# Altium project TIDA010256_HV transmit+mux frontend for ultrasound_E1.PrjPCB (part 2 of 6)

## Sheet 12_LowVoltage_PowerSupplies01.SchDoc
size 431 x 279 mm; Date: Not shown in title block; ApprovedBy: Not shown in title block; CheckedBy: Not shown in title block; Author: Not shown in title block; CompanyName: Not shown in title block; Engineer: Not shown in title block; Organization: Not shown in title block; Address1: Not shown in title block; Address2: Not shown in title block; Address3: Not shown in title block; Address4: Not shown in title block; DocumentNumber: 4; Revision: Use project parameter SCH_Rev; SheetNumber: 4; SheetTotal: 18; PageSetup: Record=PageOptions¦CenterHorizontal=True¦CenterVertical=True¦PrintScale=1.00¦XCorrection=1.00¦YCorrection=1.00¦PrintKind=0¦BorderSize=5000000¦LeftOffset=0¦BottomOffset=0¦Orientation=2¦PaperLength=1000¦PaperWidth=1000¦Scale=100¦PaperSource=15¦PrintQuality=600¦MediaType=1¦DitherType=10¦PaperKind=Letter¦PrintScaleMode=1
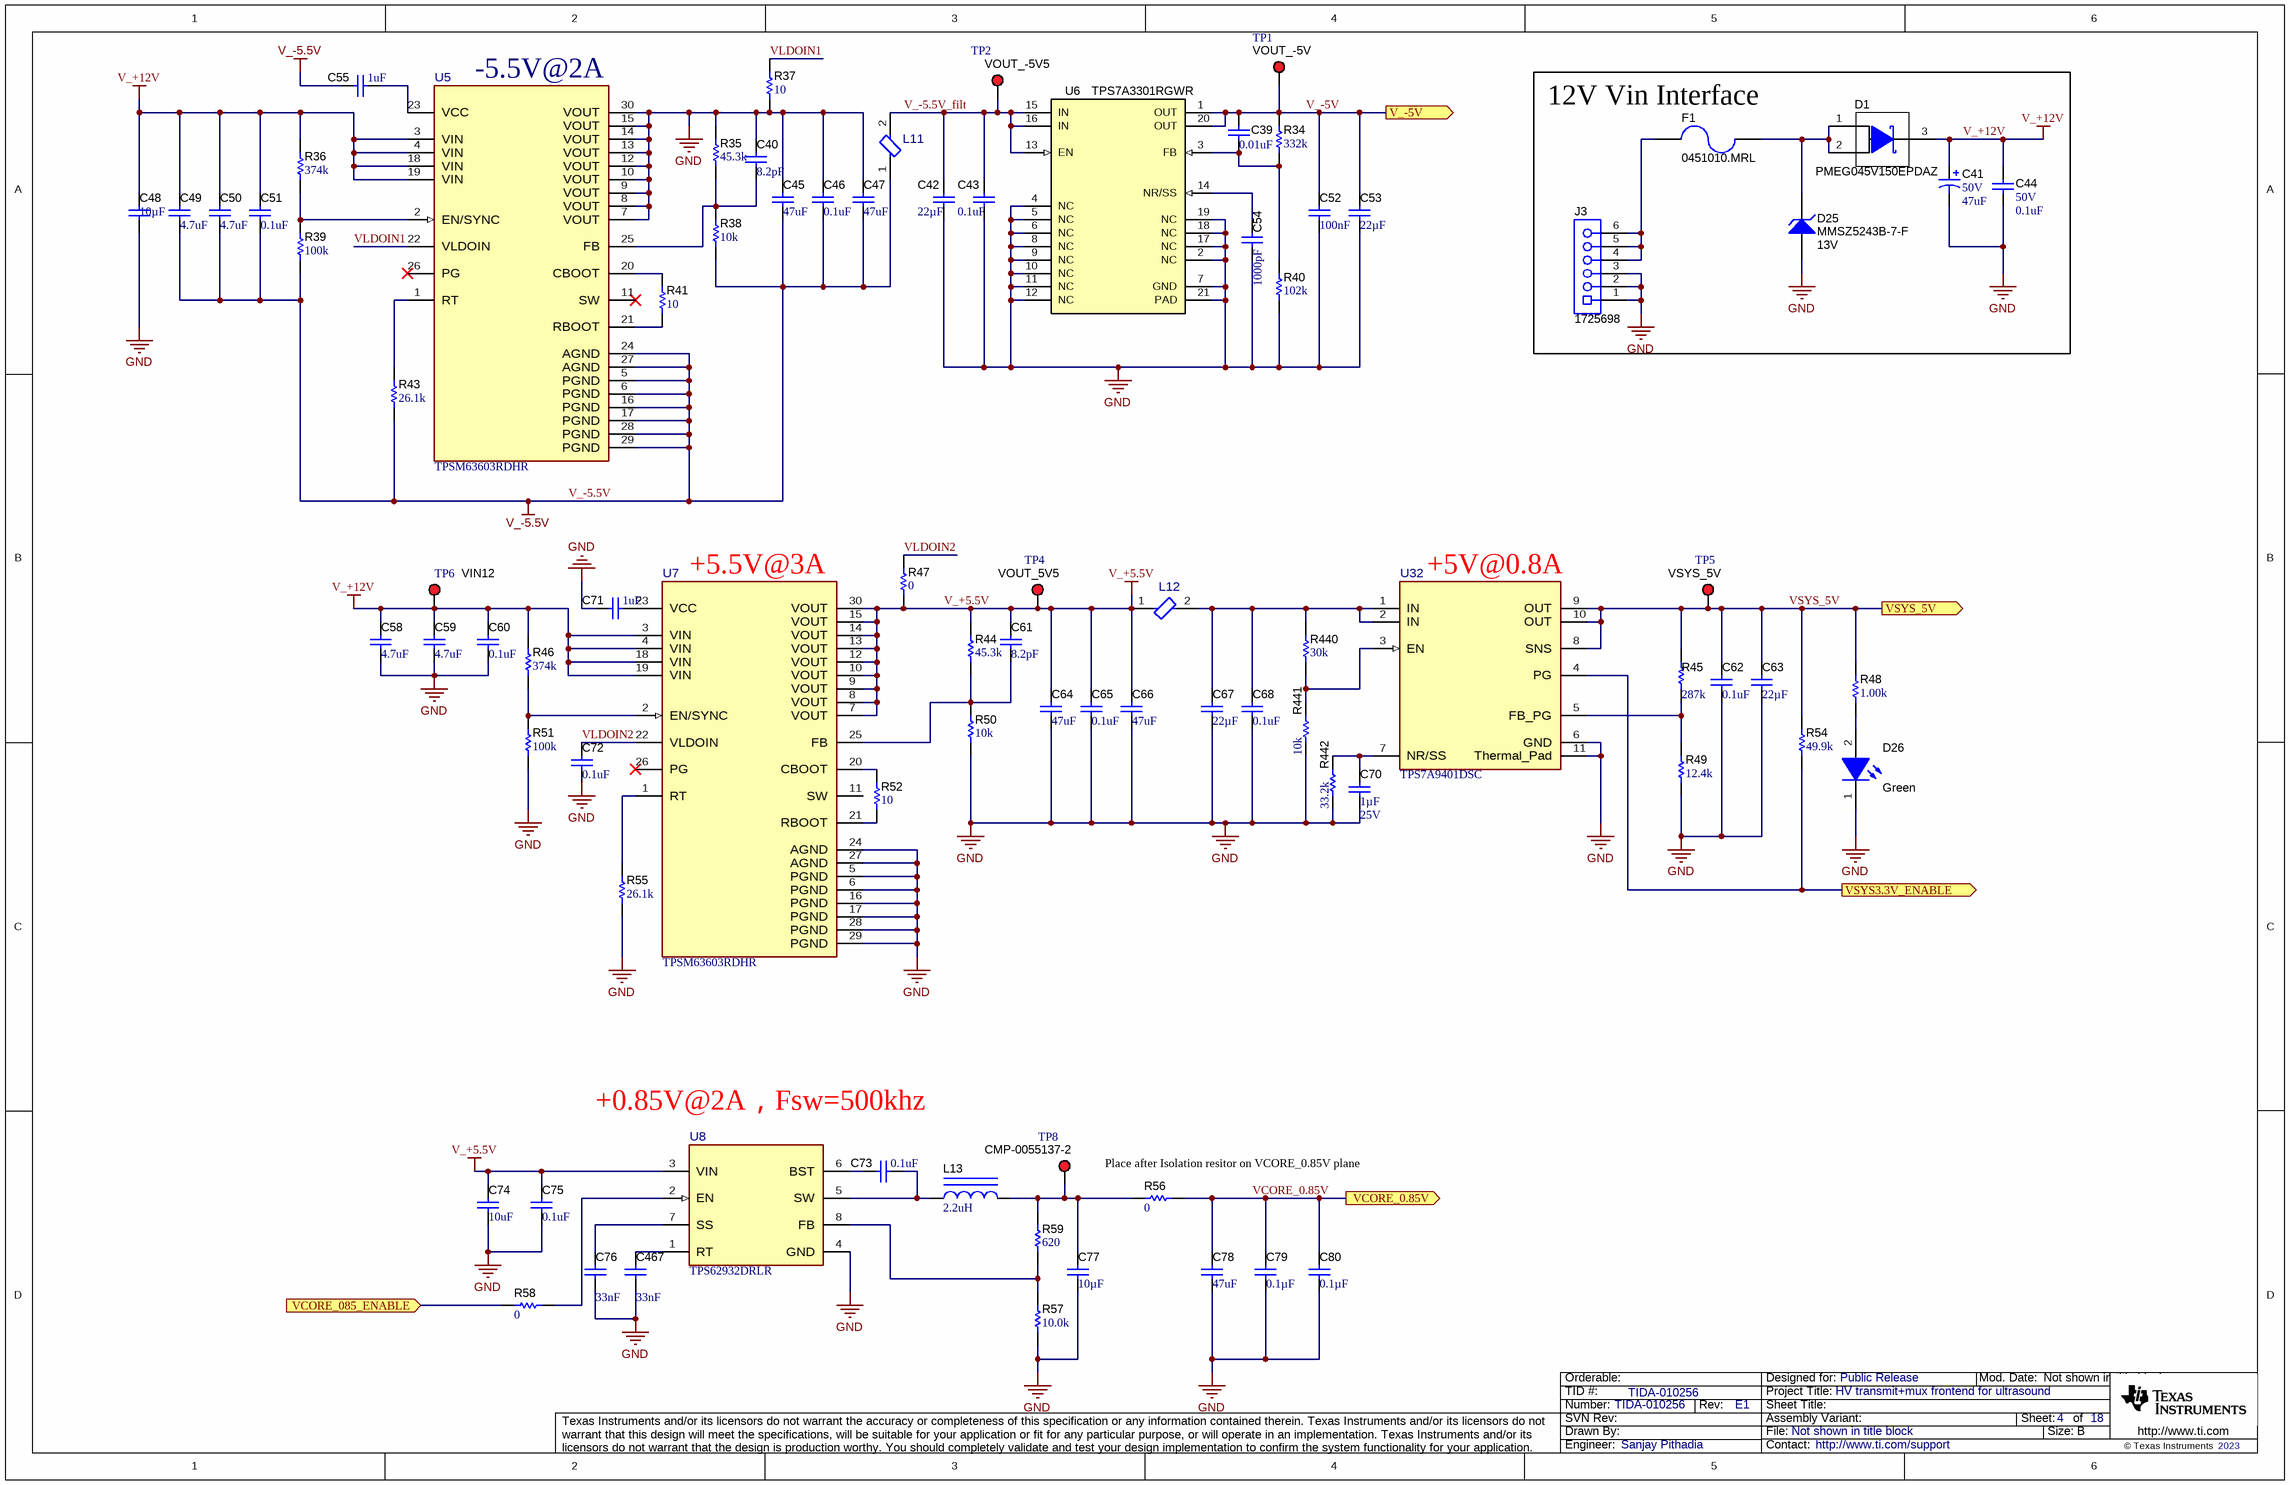
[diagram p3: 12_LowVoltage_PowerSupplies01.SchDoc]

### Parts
C39  ValueDisplayed: 0.01uF  [0603]  (hidden comment: C0603C103K4RACTU)
C40  ValueDisplayed: 8.2pF  [0402]  (hidden comment: GRM1555C1E8R2CA01D)
C41  VDC_V: 50V  ValueDisplayed: 47uF  [Panasonic_D]  (hidden comment: EEEFT1H470AP)
C42  ValueDisplayed: 22µF  [0603]  (hidden comment: CL10A226MO7JZNC)
C43  ValueDisplayed: 0.1uF  [0603]  (hidden comment: C0603C104M4RACTU)
C44  VDC_V: 50V  ValueDisplayed: 0.1uF  [0603]  (hidden comment: C1608X5R1H104K080AA)
C45  ValueDisplayed: 47uF  [1206_190]  (hidden comment: C3216X5R1E476M160AC)
C46  ValueDisplayed: 0.1uF  [0805_HV]  (hidden comment: C0805C104M5RACTU)
C47  ValueDisplayed: 47uF  [1206_190]  (hidden comment: C3216X5R1E476M160AC)
C48  ValueDisplayed: 10µF  [1206_190]  (hidden comment: UMK316BBJ106KL-T)
C49  ValueDisplayed: 4.7uF  [1206_180]  (hidden comment: C3216X7R1H475K160AC)
C50  ValueDisplayed: 4.7uF  [1206_180]  (hidden comment: C3216X7R1H475K160AC)
C51  ValueDisplayed: 0.1uF  [0805_HV]  (hidden comment: C0805C104M5RACTU)
C52  Cap_F: 100nF  [0603]  (hidden comment: C0603C104K8RACTU)
C53  ValueDisplayed: 22µF  [0603]  (hidden comment: CL10A226MO7JZNC)
C54  ValueDisplayed: 1000pF  [0603]  (hidden comment: GRM1885C1E102JA01D)
C55  ValueDisplayed: 1uF  [0402]  (hidden comment: GRM155R61E105KA12D)
C58  ValueDisplayed: 4.7uF  [1206_180]  (hidden comment: C3216X7R1H475K160AC)
C59  ValueDisplayed: 4.7uF  [1206_180]  (hidden comment: C3216X7R1H475K160AC)
C60  ValueDisplayed: 0.1uF  [0805_HV]  (hidden comment: C0805C104M5RACTU)
C61  ValueDisplayed: 8.2pF  [0402]  (hidden comment: GRM1555C1E8R2CA01D)
C62  ValueDisplayed: 0.1uF  [0603]  (hidden comment: C0603C104K8RACTU)
C63  ValueDisplayed: 22µF  [0603]  (hidden comment: CL10A226MO7JZNC)
C64  ValueDisplayed: 47uF  [1206_190]  (hidden comment: C3216X5R1E476M160AC)
C65  ValueDisplayed: 0.1uF  [0805_HV]  (hidden comment: C0805C104M5RACTU)
C66  ValueDisplayed: 47uF  [1206_190]  (hidden comment: C3216X5R1E476M160AC)
C67  ValueDisplayed: 22µF  [0603]  (hidden comment: CL10A226MO7JZNC)
C68  ValueDisplayed: 0.1uF  [0603]  (hidden comment: C0603C104M4RACTU)
C70  Cap_F: 1µF  VDC_V: 25V  [0603]  (hidden comment: 06033C105KAT2A)
C71  ValueDisplayed: 1uF  [0402]  (hidden comment: GRM155R61E105KA12D)
C72  ValueDisplayed: 0.1uF  [0402]  (hidden comment: GRM155R61E105KA12D)
C73  ValueDisplayed: 0.1uF  [0402]  (hidden comment: GRM155R71A104KA01D)
C74  ValueDisplayed: 10uF  [0805_HV]  (hidden comment: C0805C106K8PACTU)
C75  ValueDisplayed: 0.1uF  [0402]  (hidden comment: GRM155R71A104KA01D)
C76  Cap_F: 33nF  [0603]  (hidden comment: CL10B333KO8NNNC)
C77  ValueDisplayed: 10µF  [0603]  (hidden comment: GRM188R61A106KE69D)
C78  ValueDisplayed: 47uF  [0603]  (hidden comment: GRM188R60J476ME15D)
C79  ValueDisplayed: 0.1µF  [0201_033]  (hidden comment: GRM033R61C104KE14D)
C80  ValueDisplayed: 0.1µF  [0201_033]  (hidden comment: GRM033R61C104KE14D)
C467  Cap_F: 33nF  [0603]  (hidden comment: CL10B333KO8NNNC)
D1  PMEG045V150EPDAZ  [SOT1289]
D25  MMSZ5243B-7-F  value 13V  [SOD-123]
D26  value Green  [WL-SMCW_GREEN]  (hidden comment: 150060VS75000)
F1  0451010.MRL  [Fuse_451_453]
J3  1725698  [Phoenix_1725698]
L11  BLM18SG700TN1D  [FP-BLM18SG700TN1D_0603-MFG]  (value not drawn)
L12  BLM18SG700TN1D  [FP-BLM18SG700TN1D_0603-MFG]  (value not drawn)
L13  ValueDisplayed: 2.2uH  [SRU1038]  (hidden comment: SRU1038-2R2Y)
R34  ValueDisplayed: 332k  [0603]  (hidden comment: CRCW060349K9FKEA)
R35  ValueDisplayed: 45.3k  [0603]  (hidden comment: CRCW060345K3FKEA)
R36  ValueDisplayed: 374k  [0603]  (hidden comment: RT0603BRD07142KL)
R37  ValueDisplayed: 10  [0402]  (hidden comment: CRCW040210R0JNED)
R38  ValueDisplayed: 10k  [0603]  (hidden comment: CRCW060349K9FKEA)
R39  ValueDisplayed: 100k  [0603]  (hidden comment: TNPW0603100KBEEA)
R40  ValueDisplayed: 102k  [0603]  (hidden comment: CRCW060349K9FKEA)
R41  ValueDisplayed: 10  [0402]  (hidden comment: CRCW040210R0JNED)
R43  ValueDisplayed: 26.1k  [0603]  (hidden comment: RT0603BRD0726K1L)
R44  ValueDisplayed: 45.3k  [0603]  (hidden comment: CRCW060349K9FKEA)
R45  ValueDisplayed: 287k  [0603]  (hidden comment: RC0603FR-07287KL)
R46  ValueDisplayed: 374k  [0603]  (hidden comment: RT0603BRD07142KL)
R47  ValueDisplayed: 0  [0603]  (hidden comment: ERJ-3GEY0R00V)
R48  ValueDisplayed: 1.00k  [0603]  (hidden comment: RC0603FR-071KL)
R49  ValueDisplayed: 12.4k  [0603]  (hidden comment: RC0603FR-0712K4L)
R50  ValueDisplayed: 10k  [0603]  (hidden comment: CRCW060349K9FKEA)
R51  ValueDisplayed: 100k  [0603]  (hidden comment: TNPW0603100KBEEA)
R52  ValueDisplayed: 10  [0402]  (hidden comment: CRCW040210R0JNED)
R54  ValueDisplayed: 49.9k  [0603]  (hidden comment: ERJ-3EKF4992V)
R55  ValueDisplayed: 26.1k  [0603]  (hidden comment: RT0603BRD0726K1L)
R56  ValueDisplayed: 0  [1210]  (hidden comment: MCR25JZHJ000)
R57  ValueDisplayed: 10.0k  [0402]  (hidden comment: CRCW040210K0FKED)
R58  ValueDisplayed: 0  [0603]  (hidden comment: CRCW060349K9FKEA)
R59  ValueDisplayed: 620  [0603]  (hidden comment: RC0603FR-07620RL)
R440  ValueDisplayed: 30k  [0603]  (hidden comment: CRCW060330K0JNEA)
R441  ValueDisplayed: 10k  [0603]  (hidden comment: CRCW060310K0JNEA)
R442  ValueDisplayed: 33.2k  [0603]  (hidden comment: RC0603FR-0733K2L)
TP1  VOUT_-5V  [Keystone5000]
TP2  VOUT_-5V5  [Keystone5000]
TP4  VOUT_5V5  [Keystone5000]
TP5  VSYS_5V  [Keystone5000]
TP6  VIN12  [Keystone5000]
TP8  CMP-0055137-2  [Keystone5000]
U5  TPSM63603RDHR  [RDH0030A-MFG]
U6  TPS7A3301RGWR  [RGW0020A]
U7  TPSM63603RDHR  [RDH0030A-MFG]
U8  TPS62932DRLR  [DRL0008A-MFG]
U32  TPS7A9401DSC  [DSC0010J-MFG]

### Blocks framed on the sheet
12V Vin Interface: C41 C44 D1 D25 F1 J3

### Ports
V_-5V (out), VCORE_0.85V (out), VCORE_085_ENABLE (in), VSYS3.3V_ENABLE (out), VSYS_5V (out)

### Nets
GND: C40.1 C41.2(-) C42.2 C43.2 C44.2 C45.1 C46.1 C47.1 C48.2 C52.2 C53.2 C54.2 C58.2 C59.2 C60.2 C62.2 C63.2 C64.2 C65.2 C66.2 C67.2 C68.2 C70.2 C71.2 C72.2 C74.2 C75.2 C76.2 C77.2 C78.2 C79.2 C80.2 C467.2 D25.2(A) D26.1(K) J3.1 J3.2 J3.3 R35.2 R37.1 R40.1 R49.1 R50.1 R51.1 R55.1 R57.1 R441.1 R442.1 U5.7(VOUT) U5.8(VOUT) U5.9(VOUT) U5.10(VOUT) U5.12(VOUT) U5.13(VOUT) U5.14(VOUT) U5.15(VOUT) U5.30(VOUT) U6.2(NC) U6.4(NC) U6.5(NC) U6.6(NC) U6.7(GND) U6.8(NC) U6.9(NC) U6.10(NC) U6.11(NC) U6.12(NC) U6.17(NC) U6.18(NC) U6.19(NC) U6.21(PAD) U7.5(PGND) U7.6(PGND) U7.16(PGND) U7.17(PGND) U7.24(AGND) U7.27(AGND) U7.28(PGND) U7.29(PGND) U8.4(GND) U32.6(GND) U32.11(Thermal_Pad)
V_+5.5V: C61.1 C64.1 C65.1 C66.1 C74.1 C75.1 L12.1 R44.2 R47.1 TP4.1 U7.7(VOUT) U7.8(VOUT) U7.9(VOUT) U7.10(VOUT) U7.12(VOUT) U7.13(VOUT) U7.14(VOUT) U7.15(VOUT) U7.30(VOUT) U8.3(VIN)
V_+12V: C41.1(+) C44.1 C48.1 C49.1 C50.1 C51.1 C58.1 C59.1 C60.1 D1.3(K) R36.2 R46.2 TP6.1 U5.3(VIN) U5.4(VIN) U5.18(VIN) U5.19(VIN) U7.3(VIN) U7.4(VIN) U7.18(VIN) U7.19(VIN)
V_-5.5V: C45.2 C46.2 C47.2 C49.2 C50.2 C51.2 C55.2 L11.1 R38.1 R39.1 R43.1 U5.5(PGND) U5.6(PGND) U5.16(PGND) U5.17(PGND) U5.24(AGND) U5.27(AGND) U5.28(PGND) U5.29(PGND)
V_-5.5V_filt: C42.1 C43.1 L11.2 TP2.1 U6.13(EN) U6.15(IN) U6.16(IN)
V_-5V: C39.1 C52.1 C53.1 R34.2 TP1.1 U6.1(OUT) U6.20(OUT) ; port V_-5V
VCORE_0.85V: C78.1 C79.1 C80.1 R56.2 ; port VCORE_0.85V
VLDOIN1: R37.2 U5.22(VLDOIN)
VLDOIN2: C72.1 R47.2 U7.22(VLDOIN)
VSYS_5V: C62.1 C63.1 R45.2 R48.2 R54.2 TP5.1 U32.8(SNS) U32.9(OUT) U32.10(OUT) ; port VSYS_5V
NetC39_2: C39.2 R34.1 R40.2 U6.3(FB)
NetC40_2: C40.2 R35.1 R38.2 U5.25(FB)
NetC54_1: C54.1 U6.14(NR/SS)
NetC55_1: C55.1 U5.23(VCC)
NetC61_2: C61.2 R44.1 R50.2 U7.25(FB)
NetC67_1: C67.1 C68.1 L12.2 R440.2 U32.1(IN) U32.2(IN)
NetC70_1: C70.1 R442.2 U32.7(NR/SS)
NetC71_1: C71.1 U7.23(VCC)
NetC73_1: C73.1 U8.6(BST)
NetC73_2: C73.2 L13.1 U8.5(SW)
NetC76_1: C76.1 U8.7(SS)
NetC77_1: C77.1 L13.2 R56.1 R59.2 TP8.1
NetC467_1: C467.1 U8.1(RT)
NetD1_1: D1.1(A) D1.2(A) D25.1(K) F1.1
NetD26_2: D26.2(A) R48.1
NetF1_2: F1.2 J3.4 J3.5 J3.6
NetR36_1: R36.1 R39.2 U5.2(EN/SYNC)
NetR41_1: R41.1 U5.21(RBOOT)
NetR41_2: R41.2 U5.20(CBOOT)
NetR43_2: R43.2 U5.1(RT)
NetR45_1: R45.1 R49.2 U32.5(FB_PG)
NetR46_1: R46.1 R51.2 U7.2(EN/SYNC)
NetR52_1: R52.1 U7.21(RBOOT)
NetR52_2: R52.2 U7.20(CBOOT)
NetR54_1: R54.1 U32.4(PG) ; port VSYS3.3V_ENABLE
NetR55_2: R55.2 U7.1(RT)
NetR57_2: R57.2 R59.1 U8.8(FB)
NetR58_1: R58.1 U8.2(EN)
NetR58_2: R58.2 ; port VCORE_085_ENABLE
NetR440_1: R440.1 R441.2 U32.3(EN)

Not connected (* = marked no-connect by the designer): U5 11(SW)* 26(PG)*; U7 11(SW) 26(PG)*

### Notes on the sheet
- (near U5) -5.5V@2A
- (near U7) +5.5V@3A
- (near U32) +5V@0.8A
- +0.85V@2A，Fsw=500khz
- Place after Isolation resitor on VCORE_0.85V plane

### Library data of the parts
C39 = CMP-0006853-4: CAP, CERM, 0.01 uF, 16 V, +/- 10%, X7R, 0603; Manufacturer: Kemet; Polarized: N; Value: 0.01uF; U/M: EA; Cap_F: 10nF; Value1: Unknown; VDC_V: 16V; TaMin_C: -55°C; TaMax_C: 125°C; SizeArea_mm2: 1.28; SizeAreaWB_mm2: 4.68; SizeX_mm: 1.6; SizeY_mm: 0.8; SizeZ_mm: 1; AEC Category: Q200
C40 C61 = CMP-0006405-2: CAP, CERM, 8.2 pF, 25 V, +/- 5%, C0G/NP0, 0402; Manufacturer: MuRata; Polarized: N; Value: 8.2pF; U/M: EA; Value1: Unknown; VDC_V: 25V; TaMin_C: -55°C; TaMax_C: 125°C; SizeArea_mm2: 0.5; SizeAreaWB_mm2: 3; SizeX_mm: 1; SizeZ_mm: 0.6; AEC Category: Q200
C41 = CMP-0011204-2: CAP, AL, 47 uF, 50 V, +/- 20%, 0.68 ohm, AEC-Q200 Grade 2, SMD; Manufacturer: Panasonic; TaMin_C: -55°C; Polarized: Y; SizeAreaWB_mm2: 73.96; U/M: EA; Value: 47uF; TaMax_C: 105°C; SizeZ_mm: 6.1; SizeX_mm: 6.6; Cap_Case: 6.3x5.8mm; SizeArea_mm2: 43.56; CompType: Capacitor; Cap_F: 47µF; IRMS_A: 195mA; AEC Grade: 2; AEC Category: Q200; ESR_ohm: 0.68
C42 C67 = CMP-0081159-1: CAP, CERM, 22 µF, 16 V,+/- 20%, X5R, 0603; Manufacturer: Samsung; Polarized: N; Value: 22uF; U/M: EA; VDC_V: 16V; TaMin_C: -55°C; TaMax_C: 85°C; SizeArea_mm2: 1.28; SizeAreaWB_mm2: 4.68; SizeX_mm: 1.6; SizeY_mm: 0.8; SizeZ_mm: 1; AEC Category: Q200
C43 C68 = CMP-0006864-4: CAP, CERM, 0.1 uF, 16 V, +/- 20%, X7R, 0603; Manufacturer: Kemet; Polarized: N; Value: 0.1uF; U/M: EA; Cap_F: 100nF; Value1: Unknown; VDC_V: 16V; TaMin_C: -55°C; TaMax_C: 125°C; SizeArea_mm2: 1.28; SizeAreaWB_mm2: 4.68; SizeX_mm: 1.6; SizeY_mm: 0.8; SizeZ_mm: 1; AEC Category: Q200
C44 = CMP-0007010-5: CAP, CERM, 0.1 uF, 50 V, +/- 10%, X5R, 0603; Manufacturer: TDK; TaMin_C: -55°C; ESR_ohm: 0.0296; Polarized: N; SizeAreaWB_mm2: 4.68; Value1: 0.0296 ohm; U/M: EA; Value: 0.1uF; TaMax_C: 85°C; SizeZ_mm: 1; SizeX_mm: 1.6; SizeY_mm: 0.8; SizeArea_mm2: 1.28; Cap_F: 100nF; IRMS_A: 9.7199dA; AEC Category: Q200
C45 C47 C64 C66 = CMP-0008656-2: CAP, CERM, 47 uF, 25 V, +/- 20%, X5R, 1206_190; Manufacturer: TDK; Polarized: N; Value: 47uF; U/M: EA; Cap_F: 47µF; Value1: Unknown; VDC_V: 25V; TaMin_C: -55°C; TaMax_C: 85°C; Cap_Case: 1206; SizeArea_mm2: 5.12; SizeAreaWB_mm2: 10.92; SizeX_mm: 3.2; SizeY_mm: 1.6; SizeZ_mm: 1.9; AEC Category: Q200
C46 C51 C60 C65 = CMP-0007727-2: CAP, CERM, 0.1 uF, 50 V, +/- 20%, X7R, 0805; Manufacturer: Kemet; Polarized: N; Value: 0.1uF; U/M: EA; Cap_F: 100nF; ESR_ohm: 64m; Value1: 0.064 ohm; VDC_V: 50V; IRMS_A: 1.64A; TaMin_C: -55°C; TaMax_C: 125°C; Cap_Case: 0805; SizeArea_mm2: 2.5; SizeAreaWB_mm2: 6.75; SizeX_mm: 2; SizeY_mm: 1.25; SizeZ_mm: 1.45; AEC Category: Q200
C48 = CMP-0086153-1: CAP, CERM, 10 µF, 50 V,+/- 10%, X5R, 1206; Manufacturer: Taiyo Yuden; Polarized: N; Value: 10uF; U/M: EA; VDC_V: 50V; TaMin_C: -55°C; TaMax_C: 85°C; Cap_Case: 1206; SizeArea_mm2: 5.12; SizeAreaWB_mm2: 10.92; SizeX_mm: 3.2; SizeY_mm: 1.6; SizeZ_mm: 1.9; AEC Category: Q200
C49 C50 C58 C59 = CMP-0008702-2: CAP, CERM, 4.7 uF, 50 V, +/- 10%, X7R, 1206; Manufacturer: TDK; Polarized: N; Value: 4.7uF; U/M: EA; Cap_F: 4.7µF; ESR_ohm: 3.158m; Value1: 0.003158 ohm; VDC_V: 50V; IRMS_A: 4.0838A; TaMin_C: -55°C; TaMax_C: 125°C; SizeArea_mm2: 5.12; SizeAreaWB_mm2: 10.92; SizeX_mm: 3.2; SizeY_mm: 1.6; SizeZ_mm: 1.8; AEC Category: Q200
C52 = CMP-0006862-5: CAP, CERM, 0.1 uF, 10 V, +/- 10%, X7R, 0603; Manufacturer: Kemet; TaMin_C: -55°C; Polarized: N; SizeAreaWB_mm2: 4.68; Value1: Unknown; U/M: EA; Value: 0.1uF; TaMax_C: 125°C; SizeZ_mm: 1; SizeX_mm: 1.6; SizeY_mm: 0.8; Value2: 10V; SizeArea_mm2: 1.28; AEC Category: Q200
C53 C63 = CMP-0081159-1: CAP, CERM, 22 µF, 16 V,+/- 20%, X5R, 0603; Manufacturer: Samsung; Value: 22uF; VDC_V: 16V; SizeZ_mm: 1; AEC Qualified: N; SizeAreaWB_mm2: 4.68; SizeArea_mm2: 1.28; AEC Category: Q200; TaMax_C: 85°C; TaMin_C: -55°C; SizeY_mm: 0.8; U/M: EA; SizeX_mm: 1.6
C54 = CMP-0007159-4: CAP, CERM, 1000 pF, 25 V, +/- 5%, C0G/NP0, 0603; Manufacturer: MuRata; TaMin_C: -55°C; Polarized: N; SizeAreaWB_mm2: 4.68; Value1: Unknown; U/M: EA; Value: 1000pF; TaMax_C: 125°C; SizeZ_mm: 1; SizeX_mm: 1.6; SizeY_mm: 0.8; Value2: 25V; SizeArea_mm2: 1.28; Cap_F: 1nF; AEC Category: Q200
C55 C71 = CMP-0006608-2: CAP, CERM, 1 uF, 25 V, +/- 10%, X5R, 0402; Manufacturer: MuRata; Polarized: N; Value: 1uF; U/M: EA; Cap_F: 1µF; Value1: Unknown; VDC_V: 25V; TaMin_C: -55°C; TaMax_C: 85°C; SizeArea_mm2: 0.5; SizeAreaWB_mm2: 3; SizeX_mm: 1; SizeZ_mm: 0.6; AEC Category: Q200
C62 = CMP-0006862-5: CAP, CERM, 0.1 uF, 10 V, +/- 10%, X7R, 0603; Manufacturer: Kemet; Polarized: N; Value: 0.1uF; U/M: EA; Cap_F: 100nF; Value1: Unknown; VDC_V: 10V; TaMin_C: -55°C; TaMax_C: 125°C; SizeArea_mm2: 1.28; SizeAreaWB_mm2: 4.68; SizeX_mm: 1.6; SizeY_mm: 0.8; SizeZ_mm: 1; AEC Category: Q200
C70 = CMP-0006754-4: CAP, CERM, 1 uF, 25 V, +/- 10%, X7R, 0603; Manufacturer: AVX; TaMin_C: -55°C; Polarized: N; SizeAreaWB_mm2: 4.68; Value1: Unknown; U/M: EA; Value: 1uF; TaMax_C: 125°C; SizeZ_mm: 1; SizeX_mm: 1.6; SizeY_mm: 0.8; SizeArea_mm2: 1.28; AEC Category: Q200
C72 = CMP-0006608-2: CAP, CERM, 0.1 uF, 25 V, +/- 10%, X5R, 0402; Manufacturer: MuRata; Polarized: N; Value: 1uF; U/M: EA; Cap_F: 1µF; Value1: Unknown; VDC_V: 25V; TaMin_C: -55°C; TaMax_C: 85°C; SizeArea_mm2: 0.5; SizeAreaWB_mm2: 3; SizeX_mm: 1; SizeZ_mm: 0.6; AEC Category: Q200
C73 C75 = CMP-0006629-2: CAP, CERM, 0.1 uF, 10 V, +/- 10%, X7R, 0402; Manufacturer: MuRata; TaMin_C: -55°C; Polarized: N; SizeAreaWB_mm2: 3; Value1: Unknown; U/M: EA; Value: 0.1uF; TaMax_C: 125°C; SizeZ_mm: 0.6; SizeX_mm: 1; SizeY_mm: 0.5; Value2: 10V; Cap_F: 100nF; AEC Category: Q200
C74 = CMP-0007732-2: CAP, CERM, 10 uF, 10 V, +/- 10%, X5R, 0805; Manufacturer: Kemet; TaMin_C: -55°C; ESR_ohm: 3m; Polarized: N; SizeAreaWB_mm2: 6.75; Value1: 0.003 ohm; U/M: EA; Value: 10uF; TaMax_C: 85°C; SizeZ_mm: 1.45; SizeX_mm: 2; SizeY_mm: 1.25; Cap_Case: 0805; Value2: 10V; SizeArea_mm2: 2.5; Cap_F: 10µF; IRMS_A: 11.43A; AEC Category: Q200
C76 C467 = CMP-0086223-1: CAP, CERM, 0.033 µF, 16 V,+/- 10%, X7R, 0603; Manufacturer: Samsung Electro-Mechanics; SizeArea_mm2: 1.28; SizeAreaWB_mm2: 4.68; Polarized: N; SizeX_mm: 1.6; Value2: 16V; AEC Category: Q200; TaMax_C: 125°C; TaMin_C: -55°C; Value: 0.033uF; U/M: EA; SizeZ_mm: 1; SizeY_mm: 0.8
C77 = CMP-0085855-1: CAP, CERM, 10 µF, 10 V,+/- 10%, X5R, 0603; Manufacturer: MuRata; SizeX_mm: 1.6; Value2: 10V; SizeAreaWB_mm2: 4.68; Green_REACh: Incomplete; AEC Category: Q200; SizeArea_mm2: 1.28; SizeY_mm: 0.8; Green_Lifecycle: Active; TaMax_C: 85°C; Value: 10uF; U/M: EA; Polarized: N; TaMin_C: -55°C; SizeZ_mm: 1
C78 = CMP-0007313-5: CAP, CERM, 47 uF, 6.3 V, +/- 20%, X5R, 0603; Manufacturer: MuRata; TaMin_C: -55°C; Polarized: N; SizeAreaWB_mm2: 4.68; Value1: Unknown; U/M: EA; Value: 47uF; TaMax_C: 85°C; SizeZ_mm: 1; SizeX_mm: 1.6; SizeY_mm: 0.8; Value2: 6.3V; SizeArea_mm2: 1.28; Cap_F: 47µF; AEC Category: Q200
C79 C80 = CMP-0086192-1: CAP, CERM, 0.1 µF, 16 V,+/- 10%, X5R, 0201; Manufacturer: MuRata; Value2: 16V; TaMax_C: 85°C; AEC Category: Q200; U/M: EA; SizeZ_mm: 0.33; SizeArea_mm2: 0.18; Polarized: N; SizeAreaWB_mm2: 2.08; Cap_F: 100nF; Cap_Case: 0201; SizeY_mm: 0.3; SizeX_mm: 0.6; Value: 0.1uF; TaMin_C: -55°C
D1 = CMP-0077070-3: Diode, Schottky, 45 V, 15 A, AEC-Q101, CFP15; Manufacturer: Nexperia; Io_A: 15A; Vf_V: 490mV; Vr_V: 45V; SizeX_mm: 6.5; Value: 45V; SizeArea_mm2: 27.95; Green_Lifecycle: Not Set; Value2: 0.49V; AEC Category: Q101; TJmax_C: 175°C; AEC Qualified: Y; SizeY_mm: 4.3; SizeAreaWB_mm2: 53.55; SizeZ_mm: 0.82; Green_REACh: Incomplete
D25 = CMP-0005752-4: Diode, Zener, 13 V, 500 mW, SOD-123; Manufacturer: Diodes Inc.; Value1: 0.5W; SizeAreaWB_mm2: 13.095; RJA_CperW: 350; AEC Category: Q101; SizeZ_mm: 1.35; SizeX_mm: 3.85; Power_W: 500mW; SizeArea_mm2: 6.545; SizeY_mm: 1.7
D26 = CMP-0002894-2: LED, Green, SMD; Manufacturer: Wurth Elektronik; Type: AlInGaP; Value2: 2V; Io_A: 20mA; Value1: W
F1 = CMP-0082398-1: Fuse, 10 A, 125VAC/VDC, SMD; Manufacturer: Littelfuse; Fuse Technology: Board Mount; VAC_V: 125V; SizeAreaWB_mm2: 37.989; Rtyp_Ohm: 5.6m; SizeArea_mm2: 16.409; Fuse Speed: Fast; MeltingTyp: 26.46; Irating_A: 10A; TaMax_C: 125°C; SizeZ_mm: 2.94; TaMin_C: -55°C; SizeY_mm: 2.69; Interrupt_AC: 35A; SizeX_mm: 6.1; Interrupt_DC: 50A
J3 = CMP-0055512-1: Terminal Block, 6x1, 2.54mm, TH; Manufacturer: Phoenix Contact; CNHeader: FALSE; Current_A: 6A; Cert_CSA: Y; Voltage_V: 160V; Row_Count: 1; Pitch_mm: 2.54; CT: TRUE
L11 L12 = CMP-0089431-1: 70 Ohms @ 100MHz 1 Power Line Ferrite Bead 0603 (1608 Metric) 4A 20mOhm; Manufacturer: Murata; SizeZ_mm: 0.65mm; AEC Qualified: No; Tolerance_%: 25%; DCR_ohm: 20m; Impedance At Frequency: 70Ω @ 100MHz
L13 = CMP-0057236-1: Inductor, Drum Core, Ferrite, 2.2 uH, 6.5 A, 0.0077 ohm, SMD; Manufacturer: Bourns; Isat: 6.5A @ 35% inductance drop; Irms: 6.8A @ 40C rise; Green_Lifecycle: Active; SizeAreaWB_mm2: 144; DCR_ohm: 7.7m; Green_REACh: Passed; Value: 2.2uH; Imax_A: 6.5A; SizeZ_mm: 3.8; SizeX_mm: 10; SizeArea_mm2: 100; Ind_H: 2.2µH; AEC Category: Q200
R34 = CMP-0022447-4: RES, 332k, 1%, 0.1 W, AEC-Q200 Grade 0, 0603; Manufacturer: Vishay-Dale; Value: 49.9k; Value_Code: 49k9; Power_W: 100mW; Value2: 0.1W; VDC_V: 75V; TempCo: 100 ppm/C; SizeArea_mm2: 1.28; SizeX_mm: 1.6; SizeY_mm: 0.8; SizeZ_mm: 1; EIA_Code: E96; AEC Category: Q200; AEC Qualified: Y; AEC Grade: 0
R35 = CMP-0022430-4: RES, 45.3 k, 1%, 0.1 W, AEC-Q200 Grade 0, 0603; Manufacturer: Vishay-Dale; Power_W: 100mW; TempCo: 100 ppm/C; Value_Code: 45k3; Value: 45.3k; EIA_Code: E96; SizeX_mm: 1.6; SizeY_mm: 0.8; SizeZ_mm: 1; Value2: 0.1W; SizeArea_mm2: 1.28; AEC Qualified: Y; VDC_V: 75V; AEC Category: Q200; AEC Grade: 0
R36 R46 = CMP-0023744-2: RES, 374 k, 0.1%, 0.1 W, 0603; Manufacturer: Yageo America; Value: 142k; Power_W: 100mW; Value2: 0.1W; VDC_V: 75V; TempCo: 25 ppm/C; SizeArea_mm2: 1.28; SizeX_mm: 1.6; SizeY_mm: 0.8; SizeZ_mm: 1; EIA_Code: E192; U/M: EA; AEC Category: Q200
R37 R41 R52 = CMP-0026827-3: RES, 10, 5%, 0.063 W, AEC-Q200 Grade 0, 0402; Manufacturer: Vishay-Dale; Value: 10; Value_Code: 10R0; Power_W: 63mW; Value2: 0.063W; VDC_V: 50V; TempCo: 200 ppm/C; SizeArea_mm2: 0.5; SizeX_mm: 1; SizeZ_mm: 0.6; EIA_Code: E24; AEC Category: Q200; AEC Qualified: Y; AEC Grade: 0
R38 R50 = CMP-0022447-4: RES, 10 k, 1%, 0.1 W, AEC-Q200 Grade 0, 0603; Manufacturer: Vishay-Dale; Value: 49.9k; Value_Code: 49k9; Power_W: 100mW; Value2: 0.1W; VDC_V: 75V; TempCo: 100 ppm/C; SizeArea_mm2: 1.28; SizeX_mm: 1.6; SizeY_mm: 0.8; SizeZ_mm: 1; EIA_Code: E96; AEC Category: Q200; AEC Qualified: Y; AEC Grade: 0
R39 R51 = CMP-0025685-3: RES, 100 k, 0.1%, 0.1 W, AEC-Q200 Grade 1, 0603; Manufacturer: Vishay-Dale; Value: 100k; Power_W: 100mW; Value2: 0.1W; VDC_V: 75V; TempCo: 25 ppm/C; SizeArea_mm2: 1.28; SizeX_mm: 1.6; SizeY_mm: 0.8; SizeZ_mm: 1; EIA_Code: E192; U/M: EA; AEC Category: Q200; AEC Qualified: Y
R40 = CMP-0022447-4: RES, 102k, 1%, 0.1 W, AEC-Q200 Grade 0, 0603; Manufacturer: Vishay-Dale; Value: 49.9k; Value_Code: 49k9; Power_W: 100mW; Value2: 0.1W; VDC_V: 75V; TempCo: 100 ppm/C; SizeArea_mm2: 1.28; SizeX_mm: 1.6; SizeY_mm: 0.8; SizeZ_mm: 1; EIA_Code: E96; AEC Category: Q200; AEC Qualified: Y; AEC Grade: 0
R43 R55 = CMP-0024014-3: RES, 26.1 k, 0.1%, 0.1 W, 0603; Manufacturer: Yageo America; Power_W: 100mW; TempCo: 25 ppm/C; Value_Code: 26k1; U/M: EA; Value: 26.1k; EIA_Code: E192; SizeX_mm: 1.6; SizeY_mm: 0.8; SizeZ_mm: 1; Value2: 0.1W; SizeArea_mm2: 1.28; VDC_V: 75V; AEC Category: Q200
R44 = CMP-0022447-4: RES, 45.3 k, 1%, 0.1 W, AEC-Q200 Grade 0, 0603; Manufacturer: Vishay-Dale; Value: 49.9k; Value_Code: 49k9; Power_W: 100mW; Value2: 0.1W; VDC_V: 75V; TempCo: 100 ppm/C; SizeArea_mm2: 1.28; SizeX_mm: 1.6; SizeY_mm: 0.8; SizeZ_mm: 1; EIA_Code: E96; AEC Category: Q200; AEC Qualified: Y; AEC Grade: 0
R45 = CMP-0022971-4: RES, 287 k, 1%, 0.1 W, 0603; Manufacturer: Yageo; Power_W: 100mW; TempCo: 100 ppm/C; Value: 287k; EIA_Code: E96; SizeX_mm: 1.6; SizeY_mm: 0.8; SizeZ_mm: 1; Value2: 0.1W; SizeArea_mm2: 1.28; AEC Qualified: N; VDC_V: 75V; AEC Category: Q200; SizeAreaWB_mm2: 4.68
R47 = CMP-0025874-4: RES, 0, 5%, 0.1 W, AEC-Q200 Grade 0, 0603; Manufacturer: Panasonic; Power_W: 100mW; TempCo: 600 ppm/C; Value_Code: 0000; Value: 0; EIA_Code: E24; SizeX_mm: 1.6; SizeY_mm: 0.8; SizeZ_mm: 1; Value2: 0.1W; SizeArea_mm2: 1.28; AEC Qualified: Y; VDC_V: 50V; AEC Category: Q200; SizeAreaWB_mm2: 4.68
R48 = CMP-0022895-5: RES, 1.00 k, 1%, 0.1 W, 0603; Manufacturer: Yageo; Power_W: 100mW; TempCo: 100 ppm/C; Value_Code: 1k00; Value: 1.00k; EIA_Code: E96; Res_ohm: 1k; SizeX_mm: 1.6; SizeY_mm: 0.8; SizeZ_mm: 1; Value2: 0.1W; SizeArea_mm2: 1.28; AEC Qualified: N; VDC_V: 75V; AEC Category: Q200; SizeAreaWB_mm2: 4.68
R49 = CMP-0022777-5: RES, 12.4 k, 1%, 0.1 W, 0603; Manufacturer: Yageo; Power_W: 100mW; TempCo: 100 ppm/C; Value_Code: 12k4; Value: 12.4k; EIA_Code: E96; SizeX_mm: 1.6; SizeY_mm: 0.8; SizeZ_mm: 1; Value2: 0.1W; SizeArea_mm2: 1.28; AEC Qualified: N; VDC_V: 75V; AEC Category: Q200; SizeAreaWB_mm2: 4.68
R54 = CMP-0022705-3: RES, 49.9 k, 1%, 0.1 W, AEC-Q200 Grade 0, 0603; Manufacturer: Panasonic; Power_W: 100mW; TempCo: 100 ppm/C; Value_Code: 49k9; U/M: EA; Value: 49.9k; EIA_Code: E96; SizeX_mm: 1.6; SizeY_mm: 0.8; SizeZ_mm: 1; Value2: 0.1W; SizeArea_mm2: 1.28; AEC Qualified: Y; VDC_V: 75V; AEC Grade: 0; AEC Category: Q200
R56 = CMP-0015361-2: RES, 0, 5%, 0.25 W, 1210; Manufacturer: Rohm; Power_W: 250mW; TempCo: 20 ppm/C; SizeAreaWB_mm2: 14.7; Value_Code: 0000; U/M: EA; Value: 0; EIA_Code: E24; SizeX_mm: 3.2; SizeY_mm: 2.5; SizeZ_mm: 1.35; Value2: 0.25W; SizeArea_mm2: 8; VDC_V: 200V; AEC Category: Q200
R57 = CMP-0025958-3: RES, 10.0 k, 1%, 0.063 W, AEC-Q200 Grade 0, 0402; Manufacturer: Vishay-Dale; Power_W: 63mW; TempCo: 100 ppm/C; Value_Code: 10k0; Value: 10.0k; EIA_Code: E96; Res_ohm: 10k; SizeX_mm: 1; SizeY_mm: 0.5; SizeZ_mm: 0.6; Value2: 0.063W; AEC Qualified: Y; VDC_V: 50V; AEC Category: Q200; AEC Grade: 0
R58 = CMP-0022447-4: RES, 0, 1%, 0.1 W, AEC-Q200 Grade 0, 0603; Manufacturer: Vishay-Dale; Value: 49.9k; Value_Code: 49k9; Power_W: 100mW; Value2: 0.1W; VDC_V: 75V; TempCo: 100 ppm/C; SizeArea_mm2: 1.28; SizeX_mm: 1.6; SizeY_mm: 0.8; SizeZ_mm: 1; EIA_Code: E96; AEC Category: Q200; AEC Qualified: Y
R59 = CMP-0023219-5: RES, 620, 1%, 0.1 W, 0603; Manufacturer: Yageo; Power_W: 100mW; TempCo: 100 ppm/C; Value_Code: 620R; Value: 620; SizeX_mm: 1.6; SizeY_mm: 0.8; SizeZ_mm: 1; Value2: 0.1W; SizeArea_mm2: 1.28; AEC Qualified: N; VDC_V: 75V; AEC Category: Q200; SizeAreaWB_mm2: 4.68
R440 = CMP-0025782-4: RES, 30 k, 5%, 0.1 W, AEC-Q200 Grade 0, 0603; Manufacturer: Vishay-Dale; Power_W: 100mW; TempCo: 200 ppm/C; Value_Code: 30k0; Value: 30k; EIA_Code: E24; SizeX_mm: 1.6; SizeY_mm: 0.8; SizeZ_mm: 1; Value2: 0.1W; SizeArea_mm2: 1.28; AEC Qualified: Y; VDC_V: 75V; AEC Category: Q200; AEC Grade: 0
R441 = CMP-0025701-4: RES, 10 k, 5%, 0.1 W, AEC-Q200 Grade 0, 0603; Manufacturer: Vishay-Dale; Power_W: 100mW; TempCo: 200 ppm/C; Value_Code: 10k0; Value: 10k; EIA_Code: E24; SizeX_mm: 1.6; SizeY_mm: 0.8; SizeZ_mm: 1; Value2: 0.1W; SizeArea_mm2: 1.28; AEC Qualified: Y; VDC_V: 75V; AEC Category: Q200; AEC Grade: 0
R442 = CMP-0023036-5: RES, 33.2 k, 1%, 0.1 W, 0603; Manufacturer: Yageo; Power_W: 100mW; TempCo: 100 ppm/C; Value_Code: 33k2; Value: 33.2k; EIA_Code: E96; SizeX_mm: 1.6; SizeY_mm: 0.8; SizeZ_mm: 1; Value2: 0.1W; SizeArea_mm2: 1.28; AEC Qualified: N; VDC_V: 75V; AEC Category: Q200; SizeAreaWB_mm2: 4.68
TP1 TP2 TP4-TP6 TP8 = CMP-0055137-2: Test Point, Miniature, Red, TH; Manufacturer: Keystone Electronics; ContactFinish: Silver; CNHeader: FALSE; CT: TRUE; Green_Lifecycle: Active; Green_REACh: Passed
U5 U7 = CMP-0047735-1: TPSM63603 Cruzline Power Module; Manufacturer: Texas Instruments; SizeZ_mm: 1.9mm; AEC Qualified: No; Max Supply Voltage: 36V; Min Supply Voltage: 3V; Nominal Supply Current: 4uA; Number Of Outputs: 1; Output Type: AdjustableProgrammable; Output Voltage: 1-16V; Standoff Height: 0mm; Switching Frequency: 200-2200kHz; Switching Topology: Buck; TaMax_C: +105°C; TaMin_C: -40°C; TJmax_C: +125°C
U6 = CMP-0036411-3: Vin -3V to -36V, -1A, Ultra-Low-Noise, High-PSRR, Low-Dropout Linear Regulator, RGW0020A (VQFN-20); Manufacturer: Texas Instruments; CompType: IC; Vin(Min)(V): -3; AEC Category: Q200; Accuracy(%): 1.5; Vout Adj(Min)(V): -1.18; SizeY_mm: 5.0; Rating: Catalog; Vin(Max)(V): -36; SizeZ_mm: 1.0; AEC Qualified: N; Vout Adj(Max)(V): -33; Vdo(Typ)(mV): 290; Iq(Typ)(mA): 0.21; Iout(Max)(A): 1; SizeAreaWB_mm2: 49.0; SizeArea_mm2: 25.0
U8 = CMP-0094457-2: 3.8-V to 30-V, 2-A Synchronous Buck Converter in SOT583 Package; Manufacturer: Texas Instruments; SizeZ_mm: 0.6mm; Max Duty Cycle: 98%; Min Supply Voltage: 3.8V; Output Type: AdjustableProgrammable; Number Of Outputs: 1; AEC Qualified: No; AEC Category: Q200; Nominal Supply Current: 12uA; CompType: IC; Standoff Height: 0mm; TJmax_C: +150°C; Switching Frequency: 310-2100kHz; Max Supply Voltage: 30V; Output Voltage: 0.8-22V
U32 = CMP-0091022-1: 1-A, Ultra-Low Noise, Ultra-High PSRR, RF Voltage Regulator; Manufacturer: Texas Instruments; Max Supply Voltage: 5.5V; Accuracy Percentage: 1-1.5%; SizeZ_mm: 0.8mm; Output Type: AdjustableProgrammable; Min Supply Voltage: 1.7V; TJmax_C: +150°C; Dropout Voltage: 210mV; AEC Qualified: No; Standoff Height: 0mm; Output Voltage: 0.4-5.3V; Number Of Outputs: 1; Nominal Supply Current: 15-47mA

## Sheet 13_LowVoltage_PowerSupplies02.SchDoc
size 431 x 279 mm; Date: Not shown in title block; ApprovedBy: Not shown in title block; CheckedBy: Not shown in title block; Author: Not shown in title block; CompanyName: Not shown in title block; Engineer: Not shown in title block; Organization: Not shown in title block; Address1: Not shown in title block; Address2: Not shown in title block; Address3: Not shown in title block; Address4: Not shown in title block; DocumentNumber: 5; Revision: Use project parameter SCH_Rev; SheetNumber: 5; SheetTotal: 18; PageSetup: Record=PageOptions¦CenterHorizontal=True¦CenterVertical=True¦PrintScale=1.00¦XCorrection=1.00¦YCorrection=1.00¦PrintKind=0¦BorderSize=5000000¦LeftOffset=0¦BottomOffset=0¦Orientation=2¦PaperLength=1000¦PaperWidth=1000¦Scale=100¦PaperSource=15¦PrintQuality=600¦MediaType=1¦DitherType=10¦PaperKind=Letter¦PrintScaleMode=1
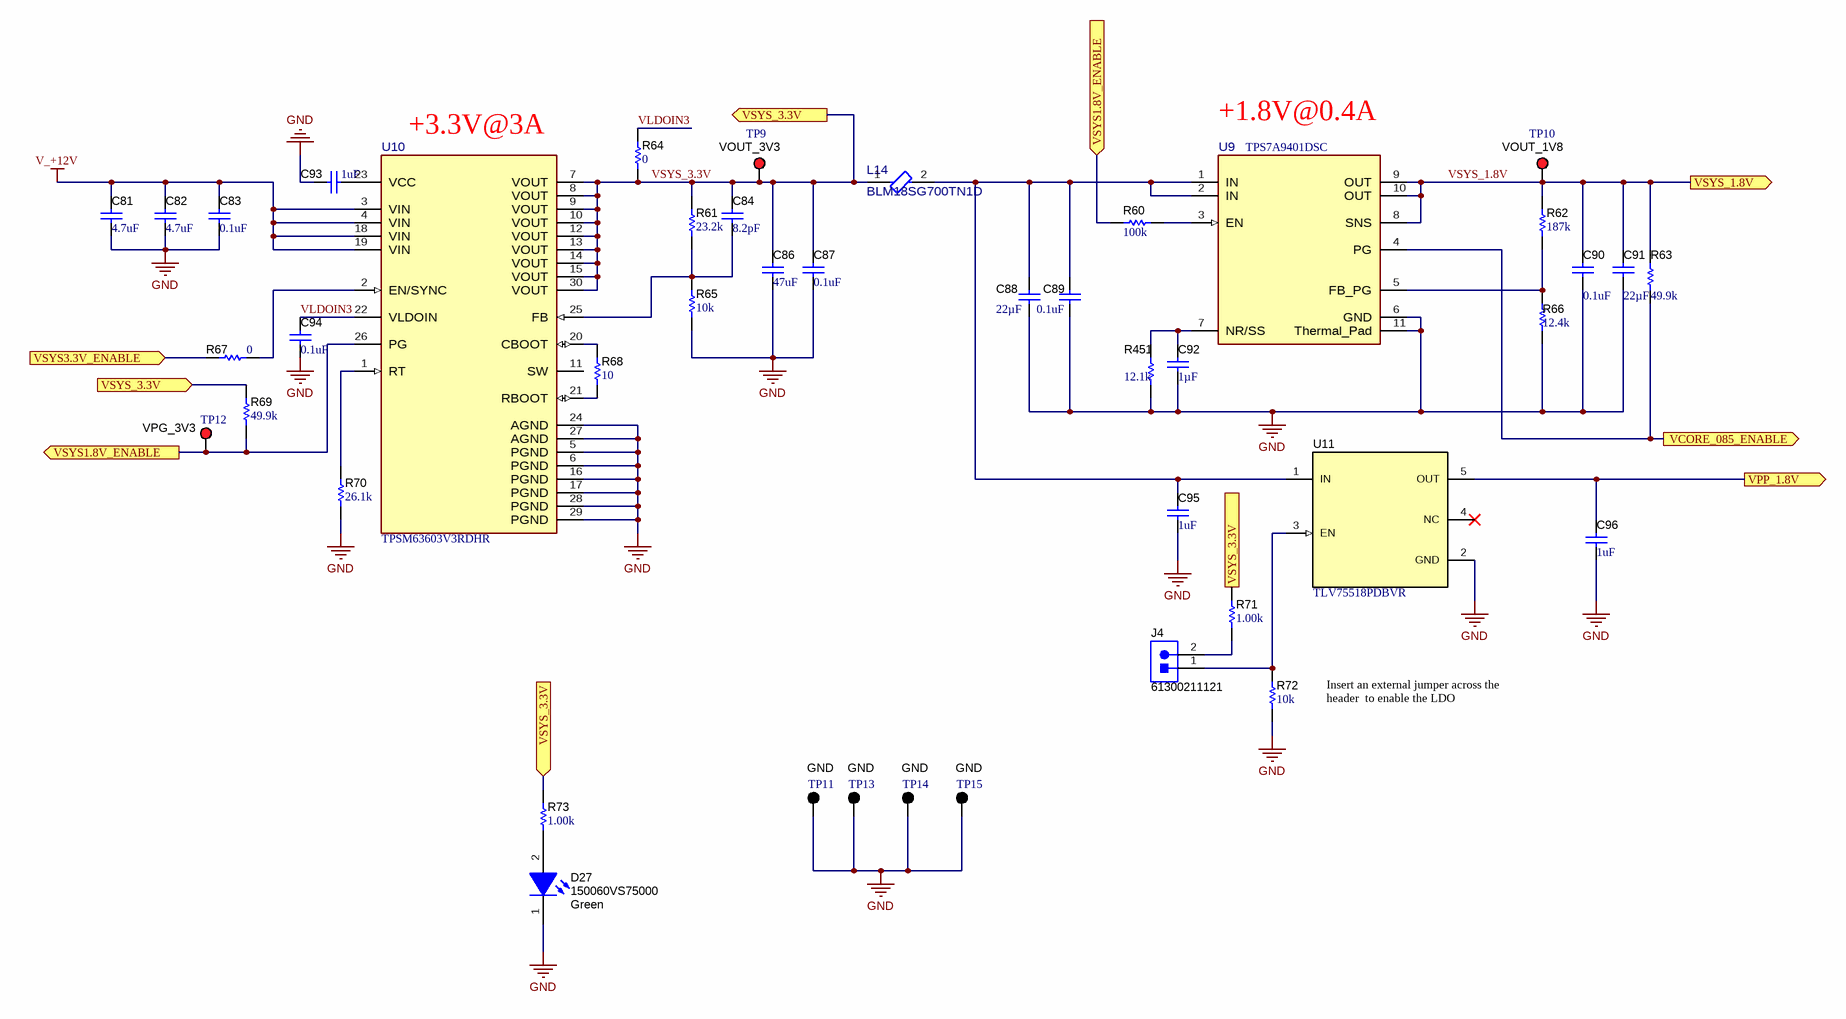
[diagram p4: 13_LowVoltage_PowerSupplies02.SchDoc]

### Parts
C81  ValueDisplayed: 4.7uF  [1206_180]  (hidden comment: C3216X7R1H475K160AC)
C82  ValueDisplayed: 4.7uF  [1206_180]  (hidden comment: C3216X7R1H475K160AC)
C83  ValueDisplayed: 0.1uF  [0805_HV]  (hidden comment: C0805C104M5RACTU)
C84  ValueDisplayed: 8.2pF  [0402]  (hidden comment: GRM1555C1E8R2CA01D)
C86  ValueDisplayed: 47uF  [1206_190]  (hidden comment: C3216X5R1E476M160AC)
C87  ValueDisplayed: 0.1uF  [0805_HV]  (hidden comment: C0805C104M5RACTU)
C88  ValueDisplayed: 22µF  [0603]  (hidden comment: CL10A226MO7JZNC)
C89  ValueDisplayed: 0.1uF  [0603]  (hidden comment: C0603C104M4RACTU)
C90  ValueDisplayed: 0.1uF  [0603]  (hidden comment: C0603C104K8RACTU)
C91  ValueDisplayed: 22µF  [0603]  (hidden comment: CL10A226MO7JZNC)
C92  Cap_F: 1µF  [0603]  (hidden comment: 06033C105KAT2A)
C93  ValueDisplayed: 1uF  [0402]  (hidden comment: GRM155R61E105KA12D)
C94  ValueDisplayed: 0.1uF  [0402]  (hidden comment: GRM155R61E105KA12D)
C95  ValueDisplayed: 1uF  [0603]  (hidden comment: C1608X5R1A105K080AC)
C96  ValueDisplayed: 1uF  [0603]  (hidden comment: C1608X5R1A105K080AC)
D27  150060VS75000  value Green  [WL-SMCW_GREEN]
J4  61300211121  [WURTH_61300211121]
L14  BLM18SG700TN1D  [FP-BLM18SG700TN1D_0603-MFG]
R60  ValueDisplayed: 100k  [0603]  (hidden comment: CRCW060349K9FKEA)
R61  ValueDisplayed: 23.2k  [0603]  (hidden comment: CRCW060349K9FKEA)
R62  ValueDisplayed: 187k  [0603]  (hidden comment: CRCW0603187KFKEA)
R63  ValueDisplayed: 49.9k  [0603]  (hidden comment: ERJ-3EKF4992V)
R64  ValueDisplayed: 0  [0603]  (hidden comment: ERJ-3GEY0R00V)
R65  ValueDisplayed: 10k  [0603]  (hidden comment: CRCW060349K9FKEA)
R66  ValueDisplayed: 12.4k  [0603]  (hidden comment: CRCW060312K4FKEA)
R67  ValueDisplayed: 0  [0603]  (hidden comment: CRCW060349K9FKEA)
R68  ValueDisplayed: 10  [0402]  (hidden comment: CRCW040210R0JNED)
R69  ValueDisplayed: 49.9k  [0603]  (hidden comment: CRCW060349K9FKEA)
R70  ValueDisplayed: 26.1k  [0603]  (hidden comment: CRCW060326K1FKEA)
R71  ValueDisplayed: 1.00k  [0603]  (hidden comment: RC0603FR-071KL)
R72  ValueDisplayed: 10k  [0603]  (hidden comment: RC0603FR-071KL)
R73  ValueDisplayed: 1.00k  [0603]  (hidden comment: RC0603FR-071KL)
R451  ValueDisplayed: 12.1k  [0603]  (hidden comment: CRCW060312K1FKEA)
TP9  VOUT_3V3  [Keystone5000]
TP10  VOUT_1V8  [Keystone5000]
TP11  GND  [Keystone5001]
TP12  VPG_3V3  [Keystone5000]
TP13  GND  [Keystone5001]
TP14  GND  [Keystone5001]
TP15  GND  [Keystone5001]
U9  TPS7A9401DSC  [DSC0010J-MFG]
U10  TPSM63603V3RDHR  [RDH0030A-MFG]
U11  TLV75518PDBVR  [DBV0005A_N]

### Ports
VCORE_085_ENABLE (out), VPP_1.8V (out), VSYS1.8V_ENABLE (in), VSYS1.8V_ENABLE (out), VSYS3.3V_ENABLE (in), VSYS_1.8V (out), VSYS_3.3V (in), VSYS_3.3V (out)

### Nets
GND: C81.2 C82.2 C83.2 C86.2 C87.2 C88.2 C89.2 C90.2 C91.2 C92.2 C93.2 C94.2 C95.2 C96.2 D27.1(K) R65.1 R66.1 R70.1 R72.1 R451.1 TP11.1 TP13.1 TP14.1 TP15.1 U9.6(GND) U9.11(Thermal_Pad) U10.5(PGND) U10.6(PGND) U10.16(PGND) U10.17(PGND) U10.24(AGND) U10.27(AGND) U10.28(PGND) U10.29(PGND) U11.2(GND)
V_+12V: C81.1 C82.1 C83.1 U10.3(VIN) U10.4(VIN) U10.18(VIN) U10.19(VIN)
VLDOIN3: C94.1 R64.2 U10.22(VLDOIN)
VSYS_1.8V: C90.1 C91.1 R62.2 R63.2 TP10.1 U9.8(SNS) U9.9(OUT) U9.10(OUT) ; port VSYS_1.8V
VSYS_3.3V: C84.1 C86.1 C87.1 L14.1 R61.2 R64.1 R69.2 R71.2 R73.2 TP9.1 U10.7(VOUT) U10.8(VOUT) U10.9(VOUT) U10.10(VOUT) U10.12(VOUT) U10.13(VOUT) U10.14(VOUT) U10.15(VOUT) U10.30(VOUT) ; port VSYS_3.3V
NetC84_2: C84.2 R61.1 R65.2 U10.25(FB)
NetC88_1: C88.1 C89.1 C95.1 L14.2 U9.1(IN) U9.2(IN) U11.1(IN)
NetC92_1: C92.1 R451.2 U9.7(NR/SS)
NetC93_1: C93.1 U10.23(VCC)
NetC96_1: C96.1 U11.5(OUT) ; port VPP_1.8V
NetD27_2: D27.2(A) R73.1
NetJ4_1: J4.1 R72.2 U11.3(EN)
NetJ4_2: J4.2 R71.1
NetR54_1: R67.2 ; port VSYS3.3V_ENABLE
NetR58_2: R63.1 U9.4(PG) ; port VCORE_085_ENABLE
NetR60_1: R60.1 U9.3(EN)
NetR60_2: R60.2 R69.1 TP12.1 U10.26(PG) ; port VSYS1.8V_ENABLE
NetR62_1: R62.1 R66.2 U9.5(FB_PG)
NetR67_1: R67.1 U10.2(EN/SYNC)
NetR68_1: R68.1 U10.21(RBOOT)
NetR68_2: R68.2 U10.20(CBOOT)
NetR70_2: R70.2 U10.1(RT)

Not connected (* = marked no-connect by the designer): U10 11(SW); U11 4(NC)*

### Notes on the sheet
- (near U10) +3.3V@3A
- +1.8V@0.4A
- Insert an external jumper across the
  header  to enable the LDO

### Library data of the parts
C81 C82 = CMP-0008702-2: as C49 on sheet 12_LowVoltage_PowerSupplies01
C83 C87 = CMP-0007727-2: as C46 on sheet 12_LowVoltage_PowerSupplies01
C84 = CMP-0006405-2: as C40 on sheet 12_LowVoltage_PowerSupplies01
C86 = CMP-0008656-2: as C45 on sheet 12_LowVoltage_PowerSupplies01
C88 = CMP-0081159-1: as C42 on sheet 12_LowVoltage_PowerSupplies01
C89 = CMP-0006864-4: as C43 on sheet 12_LowVoltage_PowerSupplies01
C90 = CMP-0006862-5: as C62 on sheet 12_LowVoltage_PowerSupplies01
C91 = CMP-0081159-1: as C53 on sheet 12_LowVoltage_PowerSupplies01
C92 = CMP-0006754-4: CAP, CERM, 1 uF, 25 V, +/- 10%, X7R, 0603; Manufacturer: AVX; TaMin_C: -55°C; Polarized: N; SizeAreaWB_mm2: 4.68; Value1: Unknown; U/M: EA; Value: 1uF; TaMax_C: 125°C; SizeZ_mm: 1; SizeX_mm: 1.6; SizeY_mm: 0.8; Value2: 25V; SizeArea_mm2: 1.28; AEC Category: Q200
C93 = CMP-0006608-2: as C55 on sheet 12_LowVoltage_PowerSupplies01
C94 = CMP-0006608-2: as C72 on sheet 12_LowVoltage_PowerSupplies01
C95 C96 = CMP-0007002-5: CAP, CERM, 1 uF, 10 V, +/- 10%, X5R, 0603; Manufacturer: TDK; TaMin_C: -55°C; Polarized: N; SizeAreaWB_mm2: 4.68; Value1: Unknown; U/M: EA; Value: 1uF; TaMax_C: 85°C; SizeZ_mm: 1; SizeX_mm: 1.6; SizeY_mm: 0.8; Value2: 10V; SizeArea_mm2: 1.28; Cap_F: 1µF; AEC Category: Q200
D27 = CMP-0002894-2: as D26 on sheet 12_LowVoltage_PowerSupplies01
J4 = CMP-0054794-2: Header, 2.54 mm, 2x1, Gold, TH; Manufacturer: Wurth Elektronik; Shrouded: N; Gender: Male; Green_REACh: Passed; Pitch_mm: 2.54; Green_Lifecycle: Active; Row_Count: 1; Cert_UL: Y
L14 = CMP-0089431-1: as L11 on sheet 12_LowVoltage_PowerSupplies01
R60 = CMP-0022447-4: RES, 100k, 1%, 0.1 W, AEC-Q200 Grade 0, 0603; Manufacturer: Vishay-Dale; Value: 49.9k; Value_Code: 49k9; Power_W: 100mW; Value2: 0.1W; VDC_V: 75V; TempCo: 100 ppm/C; SizeArea_mm2: 1.28; SizeX_mm: 1.6; SizeY_mm: 0.8; SizeZ_mm: 1; EIA_Code: E96; AEC Category: Q200; AEC Qualified: Y; AEC Grade: 0
R61 = CMP-0022447-4: RES, 23.2k, 1%, 0.1 W, AEC-Q200 Grade 0, 0603; Manufacturer: Vishay-Dale; Value: 49.9k; Value_Code: 49k9; Power_W: 100mW; Value2: 0.1W; VDC_V: 75V; TempCo: 100 ppm/C; SizeArea_mm2: 1.28; SizeX_mm: 1.6; SizeY_mm: 0.8; SizeZ_mm: 1; EIA_Code: E96; AEC Category: Q200; AEC Qualified: Y; AEC Grade: 0
R62 = CMP-0022095-4: RES, 187 k, 1%, 0.1 W, AEC-Q200 Grade 0, 0603; Manufacturer: Vishay-Dale; Power_W: 100mW; TempCo: 100 ppm/C; Value: 187k; EIA_Code: E96; SizeX_mm: 1.6; SizeY_mm: 0.8; SizeZ_mm: 1; Value2: 0.1W; SizeArea_mm2: 1.28; AEC Qualified: Y; VDC_V: 75V; AEC Category: Q200; AEC Grade: 0
R63 = CMP-0022705-3: as R54 on sheet 12_LowVoltage_PowerSupplies01
R64 = CMP-0025874-4: as R47 on sheet 12_LowVoltage_PowerSupplies01
R65 = CMP-0022447-4: as R38 on sheet 12_LowVoltage_PowerSupplies01
R66 = CMP-0022031-4: RES, 12.4 k, 1%, 0.1 W, AEC-Q200 Grade 0, 0603; Manufacturer: Vishay-Dale; Power_W: 100mW; TempCo: 100 ppm/C; Value_Code: 12k4; Value: 12.4k; EIA_Code: E96; SizeX_mm: 1.6; SizeY_mm: 0.8; SizeZ_mm: 1; Value2: 0.1W; SizeArea_mm2: 1.28; AEC Qualified: Y; VDC_V: 75V; AEC Category: Q200; AEC Grade: 0
R67 = CMP-0022447-4: as R58 on sheet 12_LowVoltage_PowerSupplies01
R68 = CMP-0026827-3: as R37 on sheet 12_LowVoltage_PowerSupplies01
R69 = CMP-0022447-4: RES, 49.9 k, 1%, 0.1 W, AEC-Q200 Grade 0, 0603; Manufacturer: Vishay-Dale; Value: 49.9k; Value_Code: 49k9; Power_W: 100mW; Value2: 0.1W; VDC_V: 75V; TempCo: 100 ppm/C; SizeArea_mm2: 1.28; SizeX_mm: 1.6; SizeY_mm: 0.8; SizeZ_mm: 1; EIA_Code: E96; AEC Category: Q200; AEC Qualified: Y; AEC Grade: 0
R70 = CMP-0022248-4: RES, 26.1 k, 1%, 0.1 W, AEC-Q200 Grade 0, 0603; Manufacturer: Vishay-Dale; Power_W: 100mW; TempCo: 100 ppm/C; Value_Code: 26k1; Value: 26.1k; EIA_Code: E96; SizeX_mm: 1.6; SizeY_mm: 0.8; SizeZ_mm: 1; Value2: 0.1W; SizeArea_mm2: 1.28; AEC Qualified: Y; VDC_V: 75V; AEC Category: Q200; AEC Grade: 0
R71 R73 = CMP-0022895-5: as R48 on sheet 12_LowVoltage_PowerSupplies01
R72 = CMP-0022895-5: RES, 10 k, 1%, 0.1 W, 0603; Manufacturer: Yageo; Power_W: 100mW; TempCo: 100 ppm/C; Value_Code: 1k00; Value: 1.00k; EIA_Code: E96; Res_ohm: 1k; SizeX_mm: 1.6; SizeY_mm: 0.8; SizeZ_mm: 1; Value2: 0.1W; SizeArea_mm2: 1.28; AEC Qualified: N; VDC_V: 75V; AEC Category: Q200; SizeAreaWB_mm2: 4.68
R451 = CMP-0022030-4: RES, 12.1 k, 1%, 0.1 W, AEC-Q200 Grade 0, 0603; Manufacturer: Vishay-Dale; Power_W: 100mW; TempCo: 100 ppm/C; Value_Code: 12k1; Value: 12.1k; EIA_Code: E96; SizeX_mm: 1.6; SizeY_mm: 0.8; SizeZ_mm: 1; Value2: 0.1W; SizeArea_mm2: 1.28; AEC Qualified: Y; VDC_V: 75V; AEC Category: Q200; AEC Grade: 0
TP9 TP10 TP12 = CMP-0055137-2: as TP1 on sheet 12_LowVoltage_PowerSupplies01
TP11 TP13-TP15 = CMP-0055138-2: Test Point, Miniature, Black, TH; Manufacturer: Keystone Electronics; ContactFinish: Silver; CNHeader: FALSE; Green_Lifecycle: Active; Green_REACh: Passed; CT: TRUE
U9 = CMP-0091022-1: as U32 on sheet 12_LowVoltage_PowerSupplies01
U10 = CMP-0093432-1: High-Density, 3-V to 36-V Input, 1-V to 16-V Output, 3-A Power Module B0QFN30; Manufacturer: Texas Instruments; SizeZ_mm: 1.9mm; Output Type: AdjustableProgrammable; TJmax_C: +150°C; Standoff Height: 0mm; Nominal Supply Current: 9uA; Switching Frequency: 200-2200kHz; TaMin_C: -40°C; Output Voltage: 1-16V; Number Of Outputs: 1; Max Duty Cycle: 98%; AEC Qualified: No; Min Supply Voltage: 3V; TaMax_C: +105°C; Switching Topology: Buck; Max Supply Voltage: 36V
U11 = CMP-0080935-1: 500-mA, Low IQ, Small Size, Low Dropout Regulator, DBV0005A (SOT-23-5); Alternate Manufacturer: Texas Instruments; SizeAreaWB_mm2: 14.82; SizeZ_mm: 1.45; SizeX_mm: 2.8; SizeY_mm: 2.9; SizeArea_mm2: 8.12; CompType: IC; AEC Qualified: N; AEC Category: Q200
